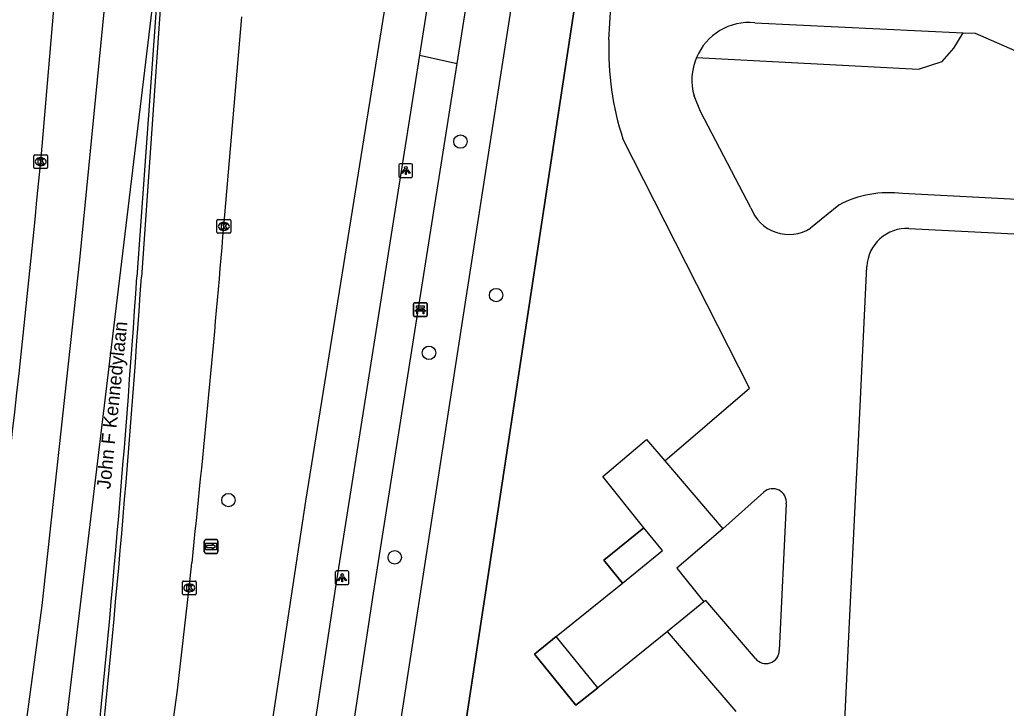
# Model space of a CAD drawing. Extents: x 161761 to 162722, y 384793 to 385405.
# Drawn here: x 161841.4 to 161913.2, y 385074 to 385124.2 of the extents above; entities that cross this region are included whole.
import ezdxf

# ---------------------------------------------------------------- set-up
doc = ezdxf.new("R2010")
doc.units = 0
for name, color, linetype in [('IMGEO_Bank', 7, 'Continuous'), ('IMGEO_Boom', 7, 'Continuous'), ('IMGEO_Erf', 7, 'Continuous'), ('IMGEO_Fietspad_open', 7, 'Continuous'), ('IMGEO_Groenvoorziening', 7, 'Continuous'), ('IMGEO_Hek', 7, 'Continuous'), ('IMGEO_Kolk', 7, 'Continuous'), ('IMGEO_Lichtpunt', 7, 'Continuous'), ('IMGEO_Openbare_ruimte_label', 7, 'Continuous'), ('IMGEO_Pand', 7, 'Continuous'), ('IMGEO_Pand_overbouw', 7, 'Continuous'), ('IMGEO_Parkeervlak_open', 7, 'Continuous'), ('IMGEO_Rijbaan_lokaal_open', 7, 'Continuous'), ('IMGEO_Rijbaan_regionaal_gesloten', 7, 'Continuous'), ('IMGEO_Voetpad_open', 7, 'Continuous'), ('IMGEO_Wegwijzer', 7, 'Continuous')]:
    doc.layers.add(name, color=color, linetype=linetype)

msp = doc.modelspace()

# ---------------------------------------------------------------- linework, layer by layer
at = {"layer": 'IMGEO_Bank'}
for p, q in [((161870.067, 385102.61), (161870.067, 385103.451)), ((161870.067, 385103.451), (161870.067, 385102.61)), ((161870.142, 385103.535), (161870.983, 385103.535)), ((161870.983, 385103.535), (161870.142, 385103.535)), ((161870.376, 385103.041), (161870.376, 385103.147)), ((161870.42, 385103.147), (161870.42, 385103.041)), ((161870.708, 385103.153), (161870.426, 385103.153)), ((161870.714, 385103.041), (161870.714, 385103.147)), ((161870.758, 385103.147), (161870.758, 385103.041)), ((161871.067, 385103.46), (161871.067, 385102.619)), ((161871.067, 385102.619), (161871.067, 385103.46)), ((161870.992, 385102.535), (161870.151, 385102.535)), ((161870.151, 385102.535), (161870.992, 385102.535)), ((161870.764, 385102.933), (161870.371, 385102.933)), ((161870.426, 385103.035), (161870.708, 385103.035))]:
    msp.add_line(p, q, dxfattribs=at)
for points in [[(161870.37, 385103.153), (161870.284, 385103.153), (161870.284, 385103.314), (161870.847, 385103.314), (161870.847, 385103.153), (161870.764, 385103.153)], [(161870.314, 385102.933), (161870.172, 385102.933), (161870.284, 385103.035), (161870.37, 385103.035)], [(161870.364, 385102.926), (161870.364, 385102.719), (161870.321, 385102.719), (161870.321, 385102.926)], [(161870.764, 385103.035), (161870.847, 385103.035), (161870.959, 385102.933), (161870.82, 385102.933)], [(161870.814, 385102.926), (161870.814, 385102.719), (161870.77, 385102.719), (161870.77, 385102.926)]]:
    msp.add_lwpolyline(points, dxfattribs=at)
for centre, radius, start, end in [((161870.145, 385103.457), 0.0779, 92.4484, 184.28452), ((161870.145, 385103.457), 0.0779, 92.4484, 184.28452), ((161870.369, 385103.146), 0.00671, 2.89567, 87.10433), ((161870.426, 385103.146), 0.00671, 92.89567, 177.10433), ((161870.708, 385103.146), 0.00671, 2.89567, 87.10433), ((161870.765, 385103.146), 0.00671, 92.89567, 177.10433), ((161870.989, 385103.457), 0.0779, 2.4484, 94.28452), ((161870.989, 385103.457), 0.0779, 2.4484, 94.28452), ((161870.145, 385102.613), 0.0779, 182.4484, 274.28452), ((161870.145, 385102.613), 0.0779, 182.4484, 274.28452), ((161870.314, 385102.926), 0.00671, 2.89567, 87.10433), ((161870.371, 385102.926), 0.00671, 92.89567, 177.10433), ((161870.369, 385103.042), 0.00671, 272.89567, 357.10433), ((161870.426, 385103.042), 0.00671, 182.89567, 267.10433), ((161870.708, 385103.042), 0.00671, 272.89567, 357.10433), ((161870.765, 385103.042), 0.00671, 182.89567, 267.10433), ((161870.763, 385102.926), 0.00671, 2.89567, 87.10433), ((161870.82, 385102.926), 0.00671, 92.89567, 177.10433), ((161870.989, 385102.613), 0.0779, 272.4484, 4.28452), ((161870.989, 385102.613), 0.0779, 272.4484, 4.28452)]:
    msp.add_arc(centre, radius, start, end, dxfattribs=at)
at = {"layer": 'IMGEO_Boom'}
for centre in [(161873.488, 385115.28), (161876.083, 385104.097), (161871.193, 385099.886), (161856.592, 385089.155), (161868.7, 385084.983)]:
    msp.add_circle(centre, 0.489, dxfattribs=at)
at = {"layer": 'IMGEO_Erf'}
for points in [[(161885.276, 385083.107), (161883.922, 385084.781), (161886.851, 385087.144)], [(161883.488, 385075.483), (161881.899, 385074.212), (161878.888, 385077.935), (161880.467, 385079.218)]]:
    msp.add_lwpolyline(points, dxfattribs=at)
at = {"layer": 'IMGEO_Fietspad_open'}
for points in [[(161842.635, 384958.805), (161843.029, 384961.875), (161848.422, 384997.787), (161862.222, 385089.066), (161867.535, 385122.216), (161881.319, 385208.219), (161882.409, 385215.357)], [(161885.4, 385214.936), (161873.913, 385143.131), (161870.503, 385121.575)], [(161870.503, 385121.575), (161864.377, 385082.843), (161845.937, 384961.055)]]:
    msp.add_lwpolyline(points, dxfattribs=at)
at = {"layer": 'IMGEO_Groenvoorziening'}
for points in [[(161913.577, 385286.213), (161913.347, 385283.925), (161913.18, 385282.726), (161892.13, 385191.383), (161887.975, 385165.729), (161880.923, 385119.329), (161863.287, 385003.273), (161862.79, 385000), (161854.635, 384944.828), (161890.389, 384901.27)], [(161888.572, 385218.345), (161891.617, 385217.57), (161876.429, 385120.298), (161873.599, 385102.176), (161860.843, 385019.372), (161853.315, 384968.451), (161850.889, 384943.599), (161852.833, 384935.577), (161860.083, 384917.83), (161874.638, 384901.508), (161887.186, 384893.396)]]:
    msp.add_lwpolyline(points, dxfattribs=at)
at = {"layer": 'IMGEO_Hek'}
for points in [[(161880.923, 385119.329), (161887.975, 385165.729), (161892.13, 385191.383), (161913.18, 385282.726), (161913.347, 385283.925)], [(161863.287, 385003.273), (161880.923, 385119.329)]]:
    msp.add_lwpolyline(points, dxfattribs=at)
at = {"layer": 'IMGEO_Kolk'}
for p, q in [((161842.42, 385113.392), (161842.42, 385114.244)), ((161842.495, 385114.318), (161843.347, 385114.318)), ((161842.908, 385114.098), (161842.933, 385114.098)), ((161843.421, 385114.244), (161843.421, 385113.392)), ((161843.347, 385113.318), (161842.495, 385113.318)), ((161842.931, 385113.538), (161842.906, 385113.538)), ((161855.829, 385109.603), (161856.681, 385109.603)), ((161855.754, 385108.677), (161855.754, 385109.529)), ((161856.242, 385109.383), (161856.267, 385109.383)), ((161856.755, 385109.529), (161856.755, 385108.677)), ((161856.681, 385108.603), (161855.829, 385108.603)), ((161856.265, 385108.823), (161856.24, 385108.823)), ((161853.242, 385082.332), (161853.242, 385083.184)), ((161853.317, 385083.258), (161854.169, 385083.258)), ((161853.73, 385083.038), (161853.755, 385083.038)), ((161854.243, 385083.184), (161854.243, 385082.332)), ((161854.169, 385082.258), (161853.317, 385082.258)), ((161853.753, 385082.478), (161853.728, 385082.478))]:
    msp.add_line(p, q, dxfattribs=at)
for points in [[(161842.42, 385113.392), (161842.42, 385114.244)], [(161842.495, 385114.318), (161843.347, 385114.318)], [(161842.741, 385114.018), (161842.864, 385114.018), (161842.864, 385113.867), (161842.994, 385114.018), (161843.158, 385114.018), (161843.012, 385113.867), (161843.165, 385113.618), (161843.013, 385113.618), (161842.928, 385113.782), (161842.864, 385113.715), (161842.864, 385113.618), (161842.741, 385113.618), (161842.741, 385114.018)], [(161843.421, 385114.244), (161843.421, 385113.392)], [(161843.347, 385113.318), (161842.495, 385113.318)], [(161855.829, 385109.603), (161856.681, 385109.603)], [(161855.754, 385108.677), (161855.754, 385109.529)], [(161856.075, 385109.303), (161856.198, 385109.303), (161856.198, 385109.152), (161856.328, 385109.303), (161856.492, 385109.303), (161856.346, 385109.152), (161856.499, 385108.903), (161856.347, 385108.903), (161856.262, 385109.067), (161856.198, 385109), (161856.198, 385108.903), (161856.075, 385108.903), (161856.075, 385109.303)], [(161856.755, 385109.529), (161856.755, 385108.677)], [(161856.681, 385108.603), (161855.829, 385108.603)], [(161853.242, 385082.332), (161853.242, 385083.184)], [(161853.317, 385083.258), (161854.169, 385083.258)], [(161854.243, 385083.184), (161854.243, 385082.332)], [(161854.169, 385082.258), (161853.317, 385082.258)], [(161853.563, 385082.958), (161853.686, 385082.958), (161853.686, 385082.807), (161853.816, 385082.958), (161853.98, 385082.958), (161853.834, 385082.807), (161853.987, 385082.558), (161853.835, 385082.558), (161853.75, 385082.722), (161853.686, 385082.655), (161853.686, 385082.558), (161853.563, 385082.558), (161853.563, 385082.958)]]:
    msp.add_lwpolyline(points, dxfattribs=at)
for centre, start, end in [((161842.497, 385114.242), 91.55205, 178.44795), ((161842.497, 385114.242), 91.55205, 178.44795), ((161843.345, 385114.242), 1.55205, 88.44795), ((161843.345, 385114.242), 1.55205, 88.44795), ((161842.497, 385113.394), 181.55205, 268.44795), ((161842.497, 385113.394), 181.55205, 268.44795), ((161843.345, 385113.394), 271.55205, 358.44795), ((161843.345, 385113.394), 271.55205, 358.44795), ((161855.831, 385109.527), 91.55205, 178.44795), ((161855.831, 385109.527), 91.55205, 178.44795), ((161856.679, 385109.527), 1.55205, 88.44795), ((161856.679, 385109.527), 1.55205, 88.44795), ((161855.831, 385108.679), 181.55205, 268.44795), ((161855.831, 385108.679), 181.55205, 268.44795), ((161856.679, 385108.679), 271.55205, 358.44795), ((161856.679, 385108.679), 271.55205, 358.44795), ((161853.319, 385083.182), 91.55205, 178.44795), ((161853.319, 385083.182), 91.55205, 178.44795), ((161854.167, 385083.182), 1.55205, 88.44795), ((161854.167, 385083.182), 1.55205, 88.44795), ((161853.319, 385082.334), 181.55205, 268.44795), ((161853.319, 385082.334), 181.55205, 268.44795), ((161854.167, 385082.334), 271.55205, 358.44795), ((161854.167, 385082.334), 271.55205, 358.44795)]:
    msp.add_arc(centre, 0.0765, start, end, dxfattribs=at)
for centre, major_axis, ratio, start_param, end_param in [((161842.907, 385113.818), (-0.387, 0.002), 0.722429, 4.712389, 7.853982), ((161842.932, 385113.818), (-0.39, 0.002), 0.717154, 1.570796, 4.712389), ((161856.241, 385109.103), (-0.387, 0.002), 0.722429, 4.712389, 7.853982), ((161856.266, 385109.103), (-0.39, 0.002), 0.717154, 1.570796, 4.712389), ((161853.729, 385082.758), (-0.387, 0.002), 0.722429, 4.712389, 7.853982), ((161853.754, 385082.758), (-0.39, 0.002), 0.717154, 1.570796, 4.712389)]:
    msp.add_ellipse(centre, major_axis=major_axis, ratio=ratio, start_param=start_param, end_param=end_param, dxfattribs=at)
at = {"layer": 'IMGEO_Lichtpunt'}
for p, q in [((161869.005, 385113.577), (161869.005, 385112.77)), ((161869.005, 385113.577), (161869.005, 385112.77)), ((161869.907, 385113.672), (161869.099, 385113.672)), ((161869.907, 385113.672), (161869.099, 385113.672)), ((161870.001, 385112.77), (161870.001, 385113.577)), ((161870.001, 385112.77), (161870.001, 385113.577)), ((161869.099, 385112.676), (161869.907, 385112.676)), ((161869.099, 385112.676), (161869.907, 385112.676)), ((161864.373, 385083.896), (161864.373, 385083.089)), ((161864.373, 385083.896), (161864.373, 385083.089)), ((161865.275, 385083.991), (161864.467, 385083.991)), ((161865.275, 385083.991), (161864.467, 385083.991)), ((161865.369, 385083.089), (161865.369, 385083.896)), ((161865.369, 385083.089), (161865.369, 385083.896)), ((161864.467, 385082.995), (161865.275, 385082.995)), ((161864.467, 385082.995), (161865.275, 385082.995))]:
    msp.add_line(p, q, dxfattribs=at)
for points in [[(161869.379, 385113.241), (161869.418, 385113.213), (161869.23, 385112.951), (161869.192, 385112.978), (161869.379, 385113.241)], [(161869.481, 385113.193), (161869.528, 385113.193), (161869.528, 385112.871), (161869.481, 385112.871), (161869.481, 385113.193)], [(161869.591, 385113.213), (161869.629, 385113.24), (161869.816, 385112.978), (161869.777, 385112.95), (161869.591, 385113.213)], [(161864.747, 385083.56), (161864.786, 385083.532), (161864.598, 385083.27), (161864.56, 385083.297), (161864.747, 385083.56)], [(161864.849, 385083.512), (161864.896, 385083.512), (161864.896, 385083.19), (161864.849, 385083.19), (161864.849, 385083.512)], [(161864.959, 385083.532), (161864.997, 385083.559), (161865.184, 385083.297), (161865.145, 385083.269), (161864.959, 385083.532)]]:
    msp.add_lwpolyline(points, dxfattribs=at)
for centre in [(161869.504, 385113.375), (161864.872, 385083.694)]:
    msp.add_circle(centre, 0.0994, dxfattribs=at)
for centre, start, end in [((161869.099, 385113.577), 90, 180), ((161869.099, 385113.577), 90, 180), ((161869.907, 385113.577), 0, 90), ((161869.907, 385113.577), 0, 90), ((161869.099, 385112.77), 180, 270), ((161869.099, 385112.77), 180, 270), ((161869.907, 385112.77), 270, 0), ((161869.907, 385112.77), 270, 360), ((161864.467, 385083.896), 90, 180), ((161864.467, 385083.896), 90, 180), ((161865.275, 385083.896), 0, 90), ((161865.275, 385083.896), 0, 90), ((161864.467, 385083.089), 180, 270), ((161864.467, 385083.089), 180, 270), ((161865.275, 385083.089), 270, 0), ((161865.275, 385083.089), 270, 360)]:
    msp.add_arc(centre, 0.0946, start, end, dxfattribs=at)
at = {"layer": 'IMGEO_Pand'}
for points in [[(161886.851, 385087.144), (161883.854, 385090.867), (161887.045, 385093.581), (161888.376, 385092.016)], [(161888.376, 385092.016), (161892.597, 385087.055)], [(161885.276, 385083.107), (161888.198, 385085.47), (161886.851, 385087.144)], [(161892.597, 385087.055), (161889.232, 385084.192), (161891.219, 385081.735)], [(161880.467, 385079.218), (161885.276, 385083.107)], [(161891.219, 385081.735), (161888.559, 385079.584)], [(161888.559, 385079.584), (161883.488, 385075.483)], [(161883.488, 385075.483), (161880.467, 385079.218)]]:
    msp.add_lwpolyline(points, dxfattribs=at)
at = {"layer": 'IMGEO_Pand_overbouw'}
for points in [[(161886.851, 385087.144), (161883.922, 385084.781), (161885.276, 385083.107), (161888.198, 385085.47)], [(161880.467, 385079.218), (161878.888, 385077.935), (161881.899, 385074.212), (161883.488, 385075.483)]]:
    msp.add_lwpolyline(points, close=True, dxfattribs=at)
at = {"layer": 'IMGEO_Parkeervlak_open'}
msp.add_lwpolyline([(161890.668, 385121.4), (161906.841, 385120.571), (161908.567, 385121.127), (161909.409, 385122.1), (161910.098, 385123.219)], dxfattribs=at)
at = {"layer": 'IMGEO_Rijbaan_lokaal_open'}
for points in [[(161856.255, 385109.103), (161857.578, 385124.362)], [(161835.818, 384961.758), (161837.654, 384973.607), (161841.441, 384998.802), (161844.782, 385021.036), (161848.122, 385043.24), (161851.205, 385063.4), (161851.83, 385067.734), (161852.871, 385075.308), (161853.743, 385082.758), (161853.937, 385084.588)]]:
    msp.add_lwpolyline(points, dxfattribs=at)
msp.add_arc((160724.749, 385203.725), 1135.456, 353.977202, 355.219785, dxfattribs=at)
at = {"layer": 'IMGEO_Rijbaan_regionaal_gesloten'}
for points in [[(161842.921, 385113.818), (161844.077, 385127.242)], [(161847.678, 385126.475), (161845.742, 385106.666), (161842.993, 385081.473), (161839.52, 385055.945), (161835.903, 385032.779), (161831.569, 385007.397), (161829.399, 384995.814), (161825.492, 384976.413), (161822.019, 384959.327), (161818.724, 384945.388), (161808.45, 384904.992), (161805.49, 384894.455), (161802.858, 384885.087)], [(161806.301, 384884.91), (161808.959, 384894.325), (161812.031, 384905.208), (161818.108, 384927.94), (161823.605, 384952.19), (161832.136, 384992.657), (161842.706, 385055.699), (161851.137, 385125.739)], [(161851.374, 385125.689), (161849.925, 385105.437)], [(161851.672, 385125.625), (161850.253, 385105.405)]]:
    msp.add_lwpolyline(points, dxfattribs=at)
for centre, radius, start, end in [((160707.489, 385222.265), 1140.599, 352.27579, 354.544128), ((160842.049, 385172.983), 1010.137, 351.628985, 356.165859), ((160824.331, 385174.832), 1028.269, 351.672196, 356.128554)]:
    msp.add_arc(centre, radius, start, end, dxfattribs=at)
at = {"layer": 'IMGEO_Voetpad_open'}
for points in [[(161873.252, 385120.982), (161876.704, 385142.872), (161881.5, 385172.372), (161888.19, 385214.465), (161888.572, 385218.345)], [(161884.296, 385122.707), (161884.498, 385126.371), (161885.217, 385132.341), (161885.62, 385134.285)], [(161894.921, 385123.946), (161910.098, 385123.219)], [(161910.098, 385123.219), (161910.965, 385123.178), (161917.901, 385120.148), (161917.248, 385110.899), (161905.688, 385111.492)], [(161870.503, 385121.575), (161873.252, 385120.982)], [(161848.857, 384961.566), (161867.164, 385082.371), (161873.252, 385120.982)], [(161894.642, 385110.454), (161890.971, 385117.483), (161890.501, 385118.615)], [(161888.376, 385092.016), (161894.546, 385097.315), (161885.315, 385115.471)], [(161901.032, 385110.651), (161898.979, 385108.966)], [(161906.144, 385108.941), (161977.597, 385105.328)], [(161901.377, 385071.009), (161901.8, 385079.731), (161902.066, 385085.225), (161902.307, 385090.208), (161902.464, 385093.454), (161903.081, 385106.189)], [(161892.597, 385087.055), (161895.578, 385089.742)], [(161897.215, 385088.886), (161896.707, 385078.188)], [(161894.966, 385077.607), (161891.349, 385081.84), (161891.219, 385081.735)], [(161893.569, 385073.753), (161888.559, 385079.584)]]:
    msp.add_lwpolyline(points, dxfattribs=at)
for centre, radius, start, end in [((161894.533, 385119.769), 4.195, 84.69353, 157.11901), ((161905.462, 385121.998), 21.177, 178.08108, 197.9507), ((161894.53, 385119.771), 4.192, 157.12944, 196.00739), ((161904.697, 385103.672), 7.883, 82.77431, 117.70324), ((161897.408, 385111.451), 2.94, 199.82318, 302.30321), ((161905.969, 385106.055), 2.891, 86.52888, 177.34832), ((161896.228, 385088.991), 0.993, 353.91353, 130.87563), ((161895.729, 385078.219), 0.978, 218.72014, 358.18924)]:
    msp.add_arc(centre, radius, start, end, dxfattribs=at)
at = {"layer": 'IMGEO_Wegwijzer'}
for p, q in [((161854.831, 385085.372), (161854.831, 385086.172)), ((161854.831, 385086.172), (161854.831, 385085.372)), ((161854.931, 385086.272), (161855.721, 385086.272)), ((161855.721, 385086.272), (161854.931, 385086.272)), ((161855.821, 385086.172), (161855.821, 385085.372)), ((161855.821, 385085.372), (161855.821, 385086.172)), ((161855.721, 385085.272), (161854.931, 385085.272)), ((161854.931, 385085.272), (161855.721, 385085.272))]:
    msp.add_line(p, q, dxfattribs=at)
for points in [[(161854.932, 385086.004), (161855.72, 385086.004), (161855.72, 385085.54), (161854.932, 385085.54), (161854.932, 385086.004)], [(161854.997, 385085.856), (161854.997, 385085.772), (161854.997, 385085.688), (161855.408, 385085.688), (161855.408, 385085.605), (161855.655, 385085.772), (161855.408, 385085.939), (161855.408, 385085.856), (161854.997, 385085.856)]]:
    msp.add_lwpolyline(points, dxfattribs=at)
for centre, start, end in [((161854.931, 385086.172), 90, 180), ((161854.931, 385086.172), 90, 180), ((161855.721, 385086.172), 0, 90), ((161855.721, 385086.172), 360, 90), ((161854.931, 385085.372), 180, 270), ((161854.931, 385085.372), 180, 270), ((161855.721, 385085.372), 270, 0), ((161855.721, 385085.372), 270, 0)]:
    msp.add_arc(centre, 0.1, start, end, dxfattribs=at)

# ---------------------------------------------------------------- texts
at = {"layer": 'IMGEO_Openbare_ruimte_label'}
msp.add_text('John F Kennedylaan', height=1, rotation=84.14691, dxfattribs=at).set_placement((161847.985, 385089.924))

doc.saveas('drawing.dxf')
